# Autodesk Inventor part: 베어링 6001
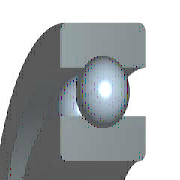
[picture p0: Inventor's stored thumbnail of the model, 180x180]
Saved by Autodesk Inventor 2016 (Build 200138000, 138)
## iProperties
IsCustomPart: 0
Created: 2015-10
Part Number: 베어링 6001
Material: 강, 연강
Description: 깊은 그루브 볼 베어링
Document SubType Name: Modeling
Standard: KS B 2023
Designer: mdu
Standards Organization: KS
Language: ko-KR
Size Designation: 6001 - 12 x 28 x 8
Categories: <MemberInstance><Categories><Category DisplayName="샤프트 부품" InternalName="7f7aeb1f-a693-4053-b835-cee3144e0d98" Mnemonic="SHFT"><Category DisplayName="베어링" Inter
Density: 1 g/cm^3
Appearance: 강철
Author: mdu
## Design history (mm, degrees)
sketch "스케치" dims "d0" = 4.16 (= -0.26 x WD + 0.26 x BD)
  geometry: L1 (1.92, 10)-(6.08, 10); L2 (4, 10)-(4, 7.92); L3 (4, 10)-(4, 12.08); L4 (2.454, 8.608)-(0, 8.608); L5 (0, 6)-(8, 6); L6 (2.454, 11.392)-(0, 11.392); L7 (0, 14)-(8, 14); L8 (8, 6)-(8, 8.608); L9 (5.546, 8.608)-(8, 8.608); L10 (5.546, 11.392)-(8, 11.392); L11 (8, 14)-(8, 11.392); L12 (-1.4, 0)-(8.4, 0) reference; L13 (0, -0.3)-(0, 5.3) reference
  constraints: 22 end point, 4 point on line, 2 collinear, 2 perpendicular, 2 symmetric about line, 1 midpoint, 1 parallel, 14 other
  dimensions: "d9" = 12 diameter of L5 L12 (= WD); "d11" = 28 diameter of L7 L12 (= BD); "d12" = 8 distance between parallel lines of L8 L13 (= KB); "d13" = 17.216 diameter of L9 L12 (= 0.326 x BD + 0.674 x WD)
revolve "본체" stored, may be unused: angle "d6" = 90 deg
revolve "볼" stored, may be unused: angle "d7" = 90 deg
pattern_circular "IDS_ARRAYBALL[SIMPL:T]" dims angle "d3" = 360 deg
body "Solid1"
fillet "모깎기1" dims "d1" = 0.3 (= KRS)
other parameters: "WD" = 12 [user parameter; used in 5 equation terms], "BD" = 28 [user parameter; used in 5 equation terms], "KB" = 8 [user parameter; used in 1 equation term], "KRS" = 0.3 [user parameter; used in 1 equation term], "d4" = 0, "d5" = 0, "d8" = 0, "d14" = 0, "d15" = 0, "BBA" = 0 [user parameter], "BC0" = 2360000 [user parameter], "BC" = 5070000 [user parameter], "BR" = 14 (= 0.5 x BD) [user parameter], "WR" = 6 (= 0.5 x WD) [user parameter]
